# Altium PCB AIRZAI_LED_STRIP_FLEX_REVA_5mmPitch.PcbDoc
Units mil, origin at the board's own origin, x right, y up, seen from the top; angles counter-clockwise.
Board outline 6238.19 x 814.96 mil, 2 copper layers (Top Layer, Bottom Layer); 59 components, 60 nets, 298 pads, 62 vias.
Unrouted connection lines stored in the file: 83.
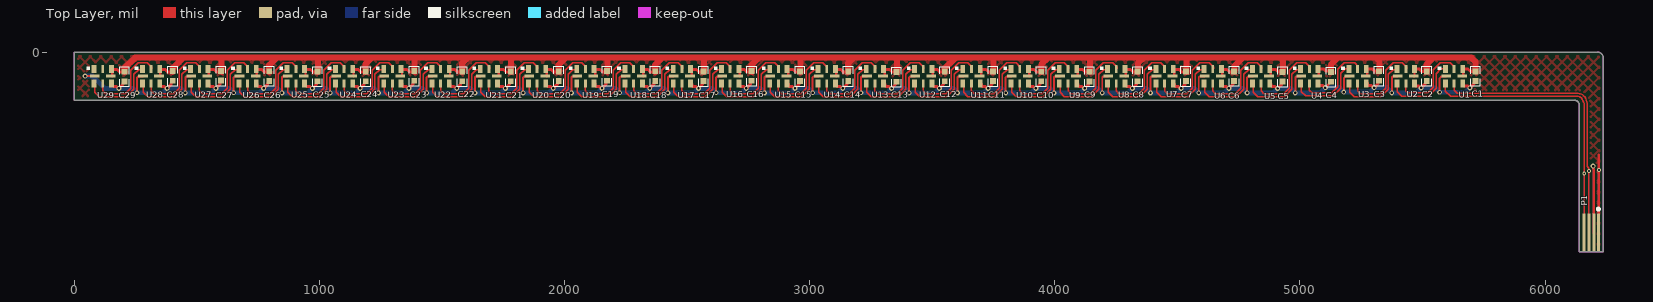
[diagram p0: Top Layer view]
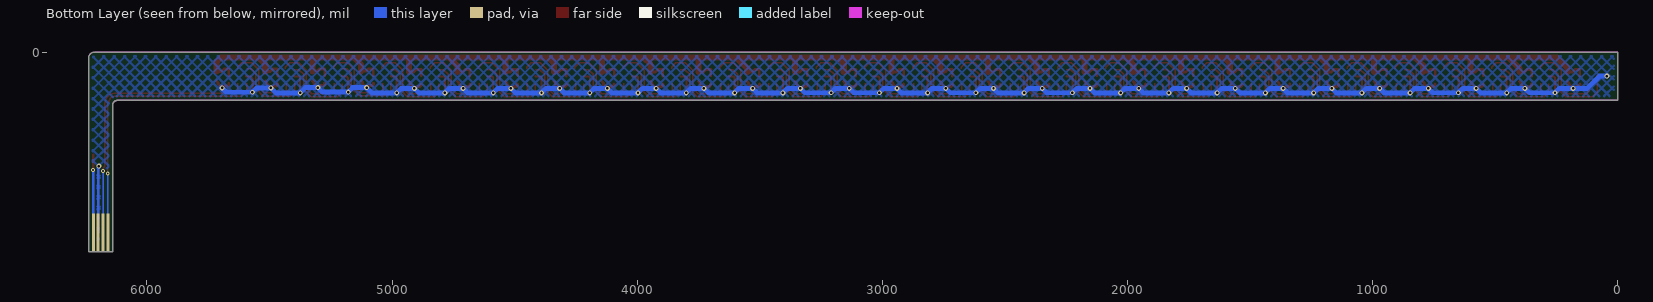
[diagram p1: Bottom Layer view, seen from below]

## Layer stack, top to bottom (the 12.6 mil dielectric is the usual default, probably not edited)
Top Solder: solder mask 0.4, Solder Resist, Dk 3.5
Top Layer: signal copper 1.4
Dielectric 1: dielectric 12.6, FR-4, Dk 4.8
Bottom Layer: signal copper 1.4
Bottom Solder: solder mask 0.4, Solder Resist, Dk 3.5

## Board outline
0,-196.85 0,0 6213.15,0 cw(c6213.15,-25.04) 6238.19,-25.04 6238.19,-814.96 6139.76,-814.96 6139.76,-216.54 ccw(c6120.08,-216.54) 6120.08,-196.85
board region "Layer Stack Region 1": 6238.19,-554.85 6238.19,-814.96 6139.76,-814.96 6139.76,-554.85
board region "Layer Stack Region 1": 6139.76,-522.85 6139.76,-216.54 6139.39,-212.7 6136.45,-205.6 6131.01,-200.17 6123.92,-197.23 6120.08,-196.85 0,-196.85 0,0 6213.15,0 6218.13,0 6227.33,-3.81 6234.38,-10.86 6238.19,-20.06 6238.19,-25.04 6238.19,-522.85
board region "Layer Stack Region 2": 6139.76,-554.85 6139.76,-522.85 6238.19,-522.85 6238.19,-554.85

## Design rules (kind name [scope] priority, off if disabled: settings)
Clearance Clearance_polygon_5V [OnLayer('Keep-Out Layer') vs (InNet('+5V') AND InPolygon)] p1: gap=10 ignorepadtopadclearanceinfootprint=FALSE
Clearance Clearance_POLYGON_KEEPOUT [(OnLayer('Keep-Out Layer')) vs (InNet('GND') AND InPolygon)] p2: gap=10 ignorepadtopadclearanceinfootprint=FALSE
Clearance [All] p3: gap=6 ignorepadtopadclearanceinfootprint=FALSE
MinimumSolderMaskSliver [All] p1: minsoldermaskwidth=1
PolygonConnect [All] p1: connectstyle=Direct reliefconductorwidth=10 reliefentries=4 polygonreliefangle="90 Angle" airgapwidth=10
RoomDefinition AIRZAI_LED_STRIP_FLEX_REVA_5mmPitch [InComponentClass('AIRZAI_LED_STRIP_FLEX_REVA_5mmPitch')] p1: confinementstyle=ConfineIn formatcopy=TRUE lockcomponents=FALSE outline -4184.14,-5323.29 10475.86,-5323.29 10475.86,4276.71 -4184.14,4276.71
RoutingVias [All] p1: holewidth=28 width=50 viastyle="Through Hole" minholewidth=8 minwidth=16 maxholewidth=28 maxwidth=50
SilkToSilkClearance [All] p1: silktosilkclearance=1
SilkToSolderMaskClearance [IsPad] p1: minsilkscreentomaskgap=2 clearancetoexposedcopper=TRUE
SolderMaskExpansion [All] p1: expansion=4
UnRoutedNet [All] p1: checkbadconnections=TRUE
Width [All] p1: maxlimit=100 minlimit=6 preferedwidth=10
26 further rules are at their usual default settings.

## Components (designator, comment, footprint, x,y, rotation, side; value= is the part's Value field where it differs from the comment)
C1 "0.1µF" 0402CAP 5716,-98.43 r270 top
C2 "0.1µF" 0402CAP 5517.17,-98.43 r270 top
C3 "0.1µF" 0402CAP 5322.3,-97.74 r270 top
C4 "0.1µF" 0402CAP 5126.94,-101.43 r270 top
C5 "0.1µF" 0402CAP 4929.6,-100.74 r270 top
C6 "0.1µF" 0402CAP 4731.75,-98.43 r270 top
C7 "0.1µF" 0402CAP 4534.9,-98.74 r270 top
C8 "0.1µF" 0402CAP 4338.05,-99.39 r270 top
C9 "0.1µF" 0402CAP 4142.2,-99.92 r270 top
C10 "0.1µF" 0402CAP 3945.35,-99.74 r270 top
C11 "0.1µF" 0402CAP 3748.17,-98.74 r270 top
C12 "0.1µF" 0402CAP 3551.65,-99.24 r270 top
C13 "0.1µF" 0402CAP 3354.8,-101.43 r270 top
C14 "0.1µF" 0402CAP 3157.43,-98.74 r270 top
C15 "0.1µF" 0402CAP 2961,-98.74 r270 top
C16 "0.1µF" 0402CAP 2763.62,-97.21 r270 top
C17 "0.1µF" 0402CAP 2567.39,-98.74 r270 top
C18 "0.1µF" 0402CAP 2370.54,-98.21 r270 top
C19 "0.1µF" 0402CAP 2174.13,-97.27 r270 top
C20 "0.1µF" 0402CAP 1976.84,-98.74 r270 top
C21 "0.1µF" 0402CAP 1780.99,-99.22 r270 top
C22 "0.1µF" 0402CAP 1583.39,-99.11 r270 top
C23 "0.1µF" 0402CAP 1387.29,-97.27 r270 top
C24 "0.1µF" 0402CAP 1189.44,-99.27 r270 top
C25 "0.1µF" 0402CAP 992.87,-98.95 r270 top
C26 "0.1µF" 0402CAP 796.06,-98.2 r270 top
C27 "0.1µF" 0402CAP 599.32,-96.9 r270 top
C28 "0.1µF" 0402CAP 402.72,-97.42 r270 top
C29 "0.1µF" 0402CAP 205.62,-100.39 r270 top
P1 "Header 4" FFC_4PADS 6188.98,-736.24 r0 top
U1 "APA102-2020-256-8" APA102–2020 5629,-98.43 r270 top
U2 "APA102-2020-256-8" APA102–2020 5432,-98.43 r270 top
U3 "APA102-2020-256-8" APA102–2020 5235.3,-98.43 r270 top
U4 "APA102-2020-256-8" APA102–2020 5038.45,-98.43 r270 top
U5 "APA102-2020-256-8" APA102–2020 4841.6,-98.43 r270 top
U6 "APA102-2020-256-8" APA102–2020 4644.75,-98.43 r270 top
U7 "APA102-2020-256-8" APA102–2020 4447.9,-98.43 r270 top
U8 "APA102-2020-256-8" APA102–2020 4251.05,-98.43 r270 top
U9 "APA102-2020-256-8" APA102–2020 4054.2,-98.42 r270 top
U10 "APA102-2020-256-8" APA102–2020 3857.35,-98.43 r270 top
U11 "APA102-2020-256-8" APA102–2020 3660.5,-98.42 r270 top
U12 "APA102-2020-256-8" APA102–2020 3463.65,-98.43 r270 top
U13 "APA102-2020-256-8" APA102–2020 3266.8,-98.42 r270 top
U14 "APA102-2020-256-8" APA102–2020 3070,-98.42 r270 top
U15 "APA102-2020-256-8" APA102–2020 2873,-98.43 r270 top
U16 "APA102-2020-256-8" APA102–2020 2676.24,-98.42 r270 top
U17 "APA102-2020-256-8" APA102–2020 2479.39,-98.43 r270 top
U18 "APA102-2020-256-8" APA102–2020 2282.54,-98.42 r270 top
U19 "APA102-2020-256-8" APA102–2020 2085.69,-98.43 r270 top
U20 "APA102-2020-256-8" APA102–2020 1888.84,-98.43 r270 top
U21 "APA102-2020-256-8" APA102–2020 1691.99,-98.43 r270 top
U22 "APA102-2020-256-8" APA102–2020 1495.14,-98.43 r270 top
U23 "APA102-2020-256-8" APA102–2020 1298.29,-98.43 r270 top
U24 "APA102-2020-256-8" APA102–2020 1101.44,-98.43 r270 top
U25 "APA102-2020-256-8" APA102–2020 904.59,-98.43 r270 top
U26 "APA102-2020-256-8" APA102–2020 707.74,-98.42 r270 top
U27 "APA102-2020-256-8" APA102–2020 510.89,-98.43 r270 top
U28 "APA102-2020-256-8" APA102–2020 314.04,-98.42 r270 top
U29 "APA102-2020-256-8" APA102–2020 117.19,-98.42 r270 top

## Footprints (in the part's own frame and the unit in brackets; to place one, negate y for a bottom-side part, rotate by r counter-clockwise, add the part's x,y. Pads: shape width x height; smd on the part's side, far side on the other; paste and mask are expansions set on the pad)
0402CAP [mm] "Chip Capacitor, Body 1.1x0.5mm, IPC High Density"
  rect 0.6x0.6 smd: 1(-0.5,0) 2(0.5,0)
  silkscreen extent -1.02,-0.51 1.02,0.51, body extent -0.5,-0.3 0.5,0.3, height 0.19
APA102–2020 [mm]
  rect 0.8x0.5 smd: 1(-0.75,0.9) 3(-0.75,-0.9) 4(0.75,-0.9) 6(0.75,0.9)
  rect 0.8x0.3 smd: 2(-0.75,0) 5(0.75,0)
  rect 0.3x1 smd: 7(0,-0.83) 8(0,0.83)
  silkscreen extent -1.02,-1.7 -0.63,-1.32, body extent -1,-1 1,1, height 0.94
FFC_4PADS [mm] "(0.50mm"
  rect 0.3x4 smd: 1(0.75,0) 2(0.25,0) 3(-0.25,0) 4(-0.75,0)
  rect 0.3x4 smd far side: 1(0.75,0) 2(0.25,0) 3(-0.25,0) 4(-0.75,0)
  silkscreen extent 0.61,2.31 0.86,2.56

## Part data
C1 C2 C3 C4 C5 C6 C7 C8 C9 C10 C11 C12 C13 C14 C15 C16 C17 C18 C19 C20 C21 C22 C23 C24 C25 C26 C27 C28 C29: library part C0402-100n, "Capacitor, X7R, ±10%", Case-EIA=0402, Case-Metric=1005, Manufacturer=TDK, Manufacturer Part Number=C1005X7R1C104K, Rated Voltage="16 V", Supplier Part Number 1=445-4952-2-ND, Tolerance=±20%
P1: "Header, 4-Pin"
U1 U2 U3 U4 U5 U6 U7 U8 U9 U10 U11 U12 U13 U14 U15 U16 U17 U18 U19 U20 U21 U22 U23 U24 U25 U26 U27 U28 U29: "DotStar Micro LEDs", Package="SOIC-20 Adafruit Industries"

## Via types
v1: diameter 20, hole 10, Top Layer to Bottom Layer, tented both sides, 59 vias
v2: diameter 16, hole 8, Top Layer to Bottom Layer, tented both sides, 3 vias

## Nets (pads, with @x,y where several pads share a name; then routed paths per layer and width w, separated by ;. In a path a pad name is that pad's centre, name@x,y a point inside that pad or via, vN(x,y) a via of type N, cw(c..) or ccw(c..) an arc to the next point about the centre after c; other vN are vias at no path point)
+5V: C1.1 C2.1 C3.1 C4.1 C5.1 C6.1 C7.1 C8.1 C9.1 C10.1 C11.1 C12.1 C13.1 C14.1 C15.1 C16.1 C17.1 C18.1 C19.1 C20.1 C21.1 C22.1 C23.1 C24.1 C25.1 C26.1 C27.1 C28.1 C29.1 P1.1 U1.1 U1.8 U2.1 U2.8 U3.1 U3.8 U4.1 U4.8 U5.1 U5.8 U6.1 U6.8 U7.1 U7.8 U8.1 U8.8 U9.1 U9.8 U10.1 U10.8 U11.1 U11.8 U12.1 U12.8 U13.1 U13.8 U14.1 U14.8 U15.1 U15.8 U16.1 U16.8 U17.1 U17.8 U18.1 U18.8 U19.1 U19.8 U20.1 U20.8 U21.1 U21.8 U22.1 U22.8 U23.1 U23.8 U24.1 U24.8 U25.1 U25.8 U26.1 U26.8 U27.1 U27.8 U28.1 U28.8 U29.1 U29.8 | length 10646.1
  Top Layer w10: U29.8@155.47,-98.42 U29.1@155.47,-71.21 ; U28.8@352.32,-98.43 U28.1@352.32,-71.21 ; U27.8@550.25,-96.85 U27.1@550.25,-71.21 ; U26.8@746.02,-98.43 U26.1@746.02,-71.21 ; U25.8@943.95,-96.85 U25.1@943.95,-71.21 ; U24.8@1139.72,-98.43 U24.1@1139.72,-71.21 ; U23.8@1337.65,-96.85 U23.1@1337.65,-71.21 ; U22.8@1533.42,-98.43 U22.1@1533.42,-71.21 ; U21.8@1731.35,-96.85 U21.1@1731.35,-71.21 ; U20.8@1927.12,-98.43 U20.1@1927.12,-71.21 ; U19.8@2125.05,-96.85 U19.1@2125.05,-71.21 ; U18.8@2320.82,-98.43 U18.1@2320.82,-71.21 ; U17.8@2518.75,-96.85 U17.1@2518.75,-71.21 ; U16.8@2714.43,-98.43 U16.1@2714.43,-71.21 ; U15.8@2912.36,-96.85 U15.1@2912.36,-71.21 ; U14.8@3108.22,-98.42 U14.1@3108.22,-71.21 ; U13.8@3306.15,-96.85 U13.1@3306.15,-71.21 ; U12.8@3501.92,-98.42 U12.1@3501.92,-71.21 ; U11.8@3699.85,-96.85 U11.1@3699.85,-71.21 ; U10.8@3895.62,-98.42 U10.1@3895.62,-71.21 ; U9.8@4093.55,-96.85 U9.1@4093.55,-71.21 ; U8.8@4289.32,-98.43 U8.1@4289.32,-71.21 ; U7.8@4487.25,-96.85 U7.1@4487.25,-71.21 ; U6.8@4683.03,-98.43 U6.1@4683.03,-71.21 ; U5.8@4880.95,-96.85 U5.1@4880.95,-71.21 ; U4.8@5073.97,-97.74 5075.82,-97.74 5076.73,-96.83 U4.1@5076.73,-68.21 ; U3.8@5274.66,-97.74 5275.56,-96.83 U3.1@5275.56,-68.21 ; U2.8 5466.53,-98.43 5467.43,-97.52 U2.1 ; U1.8@5665.36,-98.43 5666.27,-97.52 U1.1@5666.27,-68.9 ; P1.1@6218.5,-736.24 6218.5,-486.35 6218.62,-486.24 6218.62,-482 v2(6219.76,-480.85) 6219.76,-417.85
  Top Layer w12: U29.1@155.47,-71.21 175.11,-71.21 184.95,-81.05 C29.1@205.2,-81.05 ; U28.1@352.32,-71.21 371.96,-71.21 381.8,-81.05 C28.1@402.05,-81.05 ; U27.1@550.25,-71.21 570.8,-71.21 580.64,-81.05 C27.1@600.88,-81.05 ; U26.1@746.02,-71.21 765.66,-71.21 775.51,-81.05 C26.1@795.75,-81.05 ; U25.1@943.95,-71.21 964.5,-71.21 974.34,-81.05 C25.1@994.58,-81.05 ; U24.1@1139.72,-71.21 1159.36,-71.21 1169.21,-81.05 C24.1@1189.45,-81.05 ; U23.1@1337.65,-71.21 1358.2,-71.21 1368.04,-81.05 C23.1@1388.28,-81.05 ; U22.1@1533.42,-71.21 1553.06,-71.21 1562.91,-81.05 C22.1@1583.15,-81.05 ; U21.1@1731.35,-71.21 1751.9,-71.21 1761.74,-81.05 C21.1@1781.99,-81.05 ; U20.1@1927.12,-71.21 1946.77,-71.21 1956.61,-81.05 C20.1@1976.85,-81.05 ; U19.1@2125.05,-71.21 2145.6,-71.21 2155.44,-81.05 C19.1@2175.69,-81.05 ; U18.1@2320.82,-71.21 2340.47,-71.21 2350.31,-81.05 C18.1@2370.55,-81.05 ; U17.1@2518.75,-71.21 2539.3,-71.21 2549.14,-81.05 C17.1@2569.39,-81.05 ; U16.1@2714.43,-71.21 2734.07,-71.21 2743.91,-81.05 C16.1@2764.16,-81.05 ; U15.1@2912.36,-71.21 2932.91,-71.21 2942.75,-81.05 C15.1@2962.99,-81.05 ; U14.1@3108.22,-71.21 3127.87,-71.21 3137.71,-81.05 C14.1@3157.96,-81.05 ; U13.1@3306.15,-71.21 3326.7,-71.21 3336.55,-81.05 C13.1@3356.79,-81.05 ; U12.1@3501.92,-71.21 3521.57,-71.21 3531.41,-81.05 C12.1@3551.66,-81.05 ; U11.1@3699.85,-71.21 3720.4,-71.21 3730.25,-81.05 C11.1@3750.49,-81.05 ; U10.1@3895.62,-71.21 3915.27,-71.21 3925.11,-81.05 C10.1@3945.36,-81.05 ; U9.1@4093.55,-71.21 4114.1,-71.21 4123.95,-81.05 C9.1@4144.19,-81.05 ; U8.1@4289.32,-71.21 4308.97,-71.21 4318.81,-81.05 C8.1@4339.06,-81.05 ; U7.1@4487.25,-71.21 4507.8,-71.21 4517.65,-81.05 C7.1@4537.89,-81.05 ; U6.1@4683.03,-71.21 4702.67,-71.21 4712.51,-81.05 C6.1@4732.76,-81.05 ; U5.1@4880.95,-71.21 4901.51,-71.21 4911.35,-81.05 C5.1@4931.59,-81.05 ; U4.1@5076.73,-68.21 5096.37,-68.21 5106.21,-78.05 C4.1@5126.46,-78.05 ; U3.1@5275.56,-68.21 5295.21,-68.21 5305.05,-78.05 C3.1@5325.29,-78.05 ; U2.1 5487.08,-68.9 5496.92,-78.74 C2.1 ; U1.1@5666.27,-68.9 5685.91,-68.9 5695.76,-78.74 C1.1
  Top Layer w25: C29.1@205.2,-81.05 205.2,-66.86 249.41,-22.65 472.76,-22.65 ; C28.1@402.05,-81.05 402.05,-66.86 446.26,-22.65 472.76,-22.65 ; C27.1@600.88,-81.05 600.88,-28.97 594.56,-22.65 ; C26.1@795.75,-81.05 795.75,-53.01 826.11,-22.65 ; C25.1@994.58,-81.05 994.58,-24.67 992.56,-22.65 ; C24.1@1189.45,-81.05 1189.45,-48.46 1215.26,-22.65 ; 1381.34,-22.65 1388.28,-29.59 C23.1@1388.28,-81.05 ; C22.1@1583.15,-81.05 1583.15,-45.76 1606.26,-22.65 1608.96,-22.65 ; C21.1@1781.99,-81.05 1781.99,-25.29 1779.34,-22.65 ; C20.1@1976.85,-81.05 1976.85,-52.16 2006.37,-22.65 ; C19.1@2175.69,-81.05 2175.69,-26.37 2171.96,-22.65 ; C18.1@2370.55,-81.05 2370.55,-52.06 2399.96,-22.65 ; C17.1@2569.39,-81.05 2569.39,-28.47 2563.56,-22.65 ; C16.1@2764.16,-81.05 2764.16,-51.75 2793.26,-22.65 ; C15.1@2962.99,-81.05 2962.99,-28.08 2957.56,-22.65 ; C14.1@3157.96,-81.05 3157.96,-44.66 3179.96,-22.65 ; C13.1@3356.79,-81.05 3356.79,-24.88 3354.56,-22.65 ; C12.1@3551.66,-81.05 3551.66,-66.86 3595.86,-22.65 ; 3743.29,-22.65 3750.49,-29.85 C11.1@3750.49,-81.05 ; C10.1@3945.36,-81.05 3945.36,-50.68 3973.39,-22.65 ; C9.1@4144.19,-81.05 4144.19,-22.65 ; C8.1@4339.06,-81.05 4339.06,-46.56 4362.96,-22.65 4450.89,-22.65 ; C7.1@4537.89,-81.05 4537.89,-27.98 4532.56,-22.65 4450.89,-22.65 ; C6.1@4732.76,-81.05 4732.76,-57.86 4767.96,-22.65 4894.76,-22.65 ; C5.1@4931.59,-81.05 4931.59,-22.65 4894.76,-22.65 ; C4.1@5126.46,-78.05 5126.46,-51.08 5150.33,-27.21 ; C3.1@5325.29,-78.05 5325.29,-38.4 5309.55,-22.65 ; C2.1 5517.17,-50.63 5544.35,-23.44 5543.56,-22.65 ; C1.1 5716,-39.09 5699.56,-22.65 5543.56,-22.65 ; 472.76,-22.65 594.56,-22.65 ; 594.56,-22.65 826.11,-22.65 ; 826.11,-22.65 992.56,-22.65 ; 992.56,-22.65 1608.96,-22.65 ; 1608.96,-22.65 1779.34,-22.65 ; 1779.34,-22.65 2006.37,-22.65 ; 2006.37,-22.65 2171.96,-22.65 ; 2171.96,-22.65 2399.96,-22.65 ; 2399.96,-22.65 2563.56,-22.65 ; 2563.56,-22.65 2793.26,-22.65 ; 2793.26,-22.65 2957.56,-22.65 ; 2957.56,-22.65 3179.96,-22.65 ; 3179.96,-22.65 3232.76,-22.65 3354.56,-22.65 ; 3354.56,-22.65 3595.86,-22.65 ; 3595.86,-22.65 3973.39,-22.65 ; 3973.39,-22.65 4144.19,-22.65 ; 4144.19,-22.65 4450.89,-22.65 ; 4450.89,-22.65 4894.76,-22.65 ; 4894.76,-22.65 5309.55,-22.65 ; 5309.55,-22.65 5543.56,-22.65
  Bottom Layer w10: P1.1@6218.5,-736.24 6218.5,-486.35 6218.62,-486.24 6218.62,-482.22 6218.5,-482.11 v2(6219.76,-480.85)
GND: C1.2 C2.2 C3.2 C4.2 C5.2 C6.2 C7.2 C8.2 C9.2 C10.2 C11.2 C12.2 C13.2 C14.2 C15.2 C16.2 C17.2 C18.2 C19.2 C20.2 C21.2 C22.2 C23.2 C24.2 C25.2 C26.2 C27.2 C28.2 C29.2 P1.2 U1.6 U1.7 U2.6 U2.7 U3.6 U3.7 U4.6 U4.7 U5.6 U5.7 U6.6 U6.7 U7.6 U7.7 U8.6 U8.7 U9.6 U9.7 U10.6 U10.7 U11.6 U11.7 U12.6 U12.7 U13.6 U13.7 U14.6 U14.7 U15.6 U15.7 U16.6 U16.7 U17.6 U17.7 U18.6 U18.7 U19.6 U19.7 U20.6 U20.7 U21.6 U21.7 U22.6 U22.7 U23.6 U23.7 U24.6 U24.7 U25.6 U25.7 U26.6 U26.7 U27.6 U27.7 U28.6 U28.7 U29.6 U29.7 | length 11347.9
  Top Layer w8: v1(44.76,-98.43) U29.7 ; v1(256.8,-166.16) 256.8,-103.26 259.72,-100.33 279.46,-100.33 U28.7 ; v1(453.65,-166.16) 453.65,-103.26 456.57,-100.33 476.31,-100.33 U27.7 ; v1(650.5,-166.16) 650.5,-103.26 653.43,-100.33 673.16,-100.33 U26.7 ; v1(847.35,-166.16) 847.35,-103.26 850.28,-100.33 870.01,-100.33 U25.7 ; v1(1044.2,-166.16) 1044.2,-103.26 1047.13,-100.33 1066.86,-100.33 U24.7 ; v1(1241.05,-166.16) 1241.05,-103.26 1243.98,-100.33 1263.71,-100.33 U23.7 ; v1(1437.9,-166.16) 1437.9,-103.26 1440.83,-100.33 1460.56,-100.33 U22.7 ; v1(1634.75,-166.16) 1634.75,-103.26 1637.68,-100.33 1657.41,-100.33 U21.7 ; v1(1831.6,-166.16) 1831.6,-103.26 1834.53,-100.33 1854.26,-100.33 U20.7 ; v1(2028.45,-166.16) 2028.45,-103.26 2031.38,-100.33 2051.11,-100.33 U19.7 ; v1(2225.3,-166.16) 2225.3,-103.26 2228.23,-100.33 2247.96,-100.33 U18.7 ; v1(2422.15,-166.16) 2422.15,-103.26 2425.08,-100.33 2444.81,-100.33 U17.7 ; v1(2619,-166.16) 2619,-103.26 2621.93,-100.33 2641.66,-100.33 U16.7 ; v1(2815.76,-166.16) 2815.76,-103.26 2818.69,-100.33 2838.42,-100.33 U15.7 ; v1(3012.76,-166.16) 3012.76,-103.26 3015.69,-100.33 3035.42,-100.33 U14.7 ; v1(3209.55,-166.16) 3209.55,-103.26 3212.48,-100.33 3232.21,-100.33 U13.7 ; v1(3406.4,-166.16) 3406.4,-103.26 3409.33,-100.33 3429.06,-100.33 U12.7 ; v1(3603.25,-166.16) 3603.25,-103.26 3606.18,-100.33 3625.91,-100.33 U11.7 ; v1(3800.1,-166.16) 3800.1,-103.26 3803.03,-100.33 3822.76,-100.33 U10.7 ; v1(3996.96,-166.16) 3996.96,-103.26 3999.88,-100.33 4019.62,-100.33 U9.7 ; v1(4193.8,-166.16) 4193.8,-103.26 4196.73,-100.33 4216.46,-100.33 U8.7 ; v1(4390.66,-166.16) 4390.66,-103.26 4393.58,-100.33 4413.31,-100.33 U7.7 ; v1(4587.51,-166.16) 4587.51,-103.26 4590.43,-100.33 4610.17,-100.33 U6.7 ; v1(4784.36,-166.16) 4784.36,-103.26 4787.28,-100.33 4807.02,-100.33 U5.7 ; v1(4981.21,-166.16) 4981.21,-103.26 4984.13,-100.33 5003.87,-100.33 U4.7 ; v1(5179.06,-163.16) 5179.06,-106.16 5184.89,-100.33 5200.72,-100.33 U3.7 ; U3.7@5203.71,-99.64 U3.7@5205.62,-97.74 ; v1(5374.76,-166.16) 5374.76,-103.26 5377.69,-100.33 5397.42,-100.33 U2.7 ; v1(5569.76,-163.85) 5569.76,-106.85 5576.28,-100.33 5594.42,-100.33 U1.7
  Top Layer w10: v1@6197.68,-466.76 v1(6195.76,-464.85) 6195.76,-474.85 6198.82,-477.91 P1.2@6198.82,-736.24
  Top Layer w12: U29.6@155.47,-130.26 155.47,-136.17 159.31,-140.01 172.48,-140.01 180.63,-148.16 v1(182.8,-148.16) 199.39,-131.57 199.39,-126.23 C29.2@205.2,-120.42 ; U28.6@352.32,-130.26 352.32,-136.17 356.16,-140.01 369.33,-140.01 377.48,-148.16 v1(379.65,-148.16) 396.24,-131.57 396.24,-126.23 C28.2@402.05,-120.42 ; U27.6@551.15,-130.26 551.15,-136.17 554.99,-140.01 568.17,-140.01 576.32,-148.16 v1(578.48,-148.16) 595.07,-131.57 595.07,-126.23 C27.2@600.88,-120.42 ; U26.6@746.02,-130.26 746.02,-136.17 749.86,-140.01 763.03,-140.01 771.18,-148.16 v1(773.35,-148.16) 789.94,-131.57 789.94,-126.23 C26.2@795.75,-120.42 ; U25.6@944.85,-130.26 944.85,-136.17 948.69,-140.01 961.87,-140.01 970.02,-148.16 v1(972.18,-148.16) 988.77,-131.57 988.77,-126.23 C25.2@994.58,-120.42 ; U24.6@1139.72,-130.26 1139.72,-136.17 1143.56,-140.01 1156.73,-140.01 1164.88,-148.16 v1(1167.05,-148.16) 1183.64,-131.57 1183.64,-126.23 C24.2@1189.45,-120.42 ; U23.6@1338.55,-130.26 1338.55,-136.17 1342.4,-140.01 1355.57,-140.01 1363.72,-148.16 v1(1365.88,-148.16) 1382.47,-131.57 1382.47,-126.23 C23.2@1388.28,-120.42 ; U22.6@1533.42,-130.26 1533.42,-136.17 1537.26,-140.01 1550.44,-140.01 1558.58,-148.16 v1(1560.75,-148.16) 1577.34,-131.57 1577.34,-126.23 C22.2@1583.15,-120.42 ; U21.6@1732.25,-130.26 1732.25,-136.17 1736.1,-140.01 1749.27,-140.01 1757.42,-148.16 v1(1759.58,-148.16) 1776.17,-131.57 1776.17,-126.23 C21.2@1781.99,-120.42 ; U20.6@1927.12,-130.26 1927.12,-136.17 1930.96,-140.01 1944.14,-140.01 1952.29,-148.16 v1(1954.45,-148.16) 1971.04,-131.57 1971.04,-126.23 C20.2@1976.85,-120.42 ; U19.6@2125.95,-130.26 2125.95,-136.17 2129.8,-140.01 2142.97,-140.01 2151.12,-148.16 v1(2153.28,-148.16) 2169.88,-131.57 2169.88,-126.23 C19.2@2175.69,-120.42 ; U18.6@2320.82,-130.26 2320.82,-136.17 2324.66,-140.01 2337.84,-140.01 2345.99,-148.16 v1(2348.15,-148.16) 2364.74,-131.57 2364.74,-126.23 C18.2@2370.55,-120.42 ; U17.6@2519.66,-130.26 2519.66,-136.17 2523.5,-140.01 2536.67,-140.01 2544.82,-148.16 v1(2546.99,-148.16) 2563.58,-131.57 2563.58,-126.23 C17.2@2569.39,-120.42 ; U16.6@2714.43,-130.26 2714.43,-136.17 2718.27,-140.01 2731.44,-140.01 2739.59,-148.16 v1(2741.76,-148.16) 2758.35,-131.57 2758.35,-126.23 C16.2@2764.16,-120.42 ; U15.6@2913.26,-130.26 2913.26,-136.17 2917.1,-140.01 2930.28,-140.01 2938.43,-148.16 v1(2940.59,-148.16) 2957.18,-131.57 2957.18,-126.23 C15.2@2962.99,-120.42 ; U14.6@3108.22,-130.26 3108.22,-136.17 3112.07,-140.01 3125.24,-140.01 3133.39,-148.16 v1(3135.55,-148.16) 3152.14,-131.57 3152.14,-126.23 C14.2@3157.96,-120.42 ; U13.6@3307.06,-130.26 3307.06,-136.17 3310.9,-140.01 3324.07,-140.01 3332.22,-148.16 v1(3334.39,-148.16) 3350.98,-131.57 3350.98,-126.23 C13.2@3356.79,-120.42 ; U12.6@3501.92,-130.26 3501.92,-136.17 3505.77,-140.01 3518.94,-140.01 3527.09,-148.16 v1(3529.25,-148.16) 3545.84,-131.57 3545.84,-126.23 C12.2@3551.66,-120.42 ; U11.6@3700.76,-130.26 3700.76,-136.17 3704.6,-140.01 3717.77,-140.01 3725.92,-148.16 v1(3728.09,-148.16) 3744.68,-131.57 3744.68,-126.23 C11.2@3750.49,-120.42 ; U10.6@3895.62,-130.26 3895.62,-136.17 3899.47,-140.01 3912.64,-140.01 3920.79,-148.16 v1(3922.96,-148.16) 3939.55,-131.57 3939.55,-126.23 C10.2@3945.36,-120.42 ; U9.6@4094.46,-130.26 4094.46,-136.17 4098.3,-140.01 4111.48,-140.01 4119.63,-148.16 v1(4121.79,-148.16) 4138.38,-131.57 4138.38,-126.23 C9.2@4144.19,-120.42 ; U8.6@4289.32,-130.26 4289.32,-136.17 4293.17,-140.01 4306.34,-140.01 4314.49,-148.16 v1(4316.66,-148.16) 4333.25,-131.57 4333.25,-126.23 C8.2@4339.06,-120.42 ; U7.6@4488.16,-130.26 4488.16,-136.17 4492,-140.01 4505.18,-140.01 4513.32,-148.16 v1(4515.49,-148.16) 4532.08,-131.57 4532.08,-126.23 C7.2@4537.89,-120.42 ; U6.6@4683.03,-130.26 4683.03,-136.17 4686.87,-140.01 4700.04,-140.01 4708.19,-148.16 v1(4710.36,-148.16) 4726.95,-131.57 4726.95,-126.23 C6.2@4732.76,-120.42 ; U5.6@4881.86,-130.26 4881.86,-136.17 4885.7,-140.01 4898.88,-140.01 4907.03,-148.16 v1(4909.19,-148.16) 4925.78,-131.57 4925.78,-126.23 C5.2@4931.59,-120.42 ; U4.6@5076.73,-127.26 5076.73,-133.17 5080.57,-137.01 5093.74,-137.01 5101.89,-145.16 v1(5104.06,-145.16) 5120.65,-128.57 5120.65,-123.23 C4.2@5126.46,-117.42 ; U3.6@5275.56,-127.26 5275.56,-133.17 5279.4,-137.01 5292.58,-137.01 5300.73,-145.16 v1(5302.89,-145.16) 5319.48,-128.57 5319.48,-123.23 C3.2@5325.29,-117.42 ; U2.6 5467.43,-133.86 5471.28,-137.7 5484.45,-137.7 5492.6,-145.85 v1(5494.76,-145.85) 5511.35,-129.26 5511.35,-123.92 C2.2 ; U1.6@5666.27,-127.95 5666.27,-133.86 5670.11,-137.7 5683.28,-137.7 5691.43,-145.85 v1(5693.6,-145.85) 5710.19,-129.26 5710.19,-123.92 C1.2
  Bottom Layer w10: P1.2@6198.82,-736.24 6198.82,-474.98
  Bottom Layer w20: v1(44.76,-98.43) 75.34,-98.43 125.07,-148.16 v1(182.8,-148.16) 238.8,-148.16 v1(256.8,-166.16) 361.65,-166.16 v1(379.65,-148.16) 435.65,-148.16 v1(453.65,-166.16) 560.48,-166.16 v1(578.48,-148.16) 632.5,-148.16 v1(650.5,-166.16) 755.35,-166.16 v1(773.35,-148.16) 829.35,-148.16 v1(847.35,-166.16) 954.18,-166.16 v1(972.18,-148.16) 1026.2,-148.16 v1(1044.2,-166.16) 1149.05,-166.16 v1(1167.05,-148.16) 1223.05,-148.16 v1(1241.05,-166.16) 1347.88,-166.16 v1(1365.88,-148.16) 1419.9,-148.16 v1(1437.9,-166.16) 1542.75,-166.16 v1(1560.75,-148.16) 1616.75,-148.16 v1(1634.75,-166.16) 1741.58,-166.16 v1(1759.58,-148.16) 1813.6,-148.16 v1(1831.6,-166.16) 1936.45,-166.16 v1(1954.45,-148.16) 2010.45,-148.16 v1(2028.45,-166.16) 2135.28,-166.16 v1(2153.28,-148.16) 2207.3,-148.16 v1(2225.3,-166.16) 2330.15,-166.16 v1(2348.15,-148.16) 2404.15,-148.16 v1(2422.15,-166.16) 2528.99,-166.16 v1(2546.99,-148.16) 2601,-148.16 v1(2619,-166.16) 2723.76,-166.16 v1(2741.76,-148.16) 2797.76,-148.16 v1(2815.76,-166.16) 2922.59,-166.16 v1(2940.59,-148.16) 2994.76,-148.16 v1(3012.76,-166.16) 3117.55,-166.16 v1(3135.55,-148.16) 3191.55,-148.16 v1(3209.55,-166.16) 3316.39,-166.16 v1(3334.39,-148.16) 3388.4,-148.16 v1(3406.4,-166.16) 3511.25,-166.16 v1(3529.25,-148.16) 3585.25,-148.16 v1(3603.25,-166.16) 3710.09,-166.16 v1(3728.09,-148.16) 3782.1,-148.16 v1(3800.1,-166.16) 3904.96,-166.16 v1(3922.96,-148.16) 3978.96,-148.16 v1(3996.96,-166.16) 4103.79,-166.16 v1(4121.79,-148.16) 4175.8,-148.16 v1(4193.8,-166.16) 4298.66,-166.16 v1(4316.66,-148.16) 4372.66,-148.16 v1(4390.66,-166.16) 4497.49,-166.16 v1(4515.49,-148.16) 4569.51,-148.16 v1(4587.51,-166.16) 4692.36,-166.16 v1(4710.36,-148.16) 4766.36,-148.16 v1(4784.36,-166.16) 4891.19,-166.16 v1(4909.19,-148.16) 4963.21,-148.16 v1(4981.21,-166.16) 5083.06,-166.16 v1(5104.06,-145.16) 5161.06,-145.16 v1(5179.06,-163.16) 5284.89,-163.16 v1(5302.89,-145.16) 5353.76,-145.16 v1(5374.76,-166.16) 5474.45,-166.16 v1(5494.76,-145.85) 5551.76,-145.85 v1(5569.76,-163.85) 5675.6,-163.85 v1(5693.6,-145.85)
LED_CLK_IN: P1.3 U1.5 | length 1379.3
  Top Layer w6: U1.5 5629,-156.09 5641.76,-168.85 6135.04,-168.85 cw(c6135.04,-199.58) 6156.76,-177.85 cw(c6118.14,-216.48) 6172.76,-216.48 6172.76,-463.19 ccw(c6186.42,-463.19) 6176.76,-472.85 cw(c6171.04,-478.57) 6179.13,-478.57 v2(6179.13,-484.85) P1.3@6179.13,-736.24
  Bottom Layer w6: P1.3@6179.13,-736.24 v2(6179.13,-484.85)
LED_CLK_OUT1: U1.2 U2.5 | length 339.5
  Top Layer w6: U2.5 5432,-158.7 5440.15,-166.85 5520.76,-166.85 5544.26,-143.35 5544.26,-71.35 5571.46,-44.15 5613.06,-44.15 5629,-60.09 U1.2
LED_CLK_OUT2: U2.2 U3.5 | length 342.6
  Top Layer w6: U3.5@5235.15,-127.95 5235.15,-158.17 5246.14,-169.16 5326.76,-169.16 5349.17,-146.75 5349.17,-74.75 5379.77,-44.15 5416.75,-44.15 5434.99,-62.4 U2.2@5434.99,-68.9
LED_CLK_OUT3: U3.2 U4.5 | length 339.5
  Top Layer w6: U4.5 5038.45,-155.17 5049.44,-166.16 5130.06,-166.16 5154.06,-142.16 5154.06,-70.16 5180.07,-44.15 5223.05,-44.15 5238.29,-59.4 U3.2@5238.29,-68.21
LED_CLK_OUT4: U4.2 U5.5 | length 342.6
  Top Layer w6: U5.5 4841.6,-158.17 4852.59,-169.16 4933.21,-169.16 4955.61,-146.75 4955.61,-74.75 4986.22,-44.15 5023.2,-44.15 5041.44,-62.4 U4.2@5041.44,-68.9
LED_CLK_OUT5: U5.2 U6.5 | length 342.6
  Top Layer w6: U6.5 4644.75,-158.17 4655.74,-169.16 4736.36,-169.16 4758.76,-146.75 4758.76,-74.75 4789.37,-44.15 4826.34,-44.15 4844.59,-62.4 U5.2@4844.59,-68.9
LED_CLK_OUT6: U6.2 U7.5 | length 342.6
  Top Layer w6: U7.5 4447.9,-158.17 4458.89,-169.16 4539.51,-169.16 4561.91,-146.75 4561.91,-74.75 4592.52,-44.15 4629.49,-44.15 4647.74,-62.4 U6.2@4647.74,-68.9
LED_CLK_OUT7: U7.2 U8.5 | length 342.6
  Top Layer w6: U8.5 4251.05,-158.17 4262.04,-169.16 4342.66,-169.16 4365.06,-146.75 4365.06,-74.75 4395.67,-44.15 4432.64,-44.15 4450.89,-62.4 U7.2@4450.89,-68.9
LED_CLK_OUT8: U8.2 U9.5 | length 342.6
  Top Layer w6: U9.5 4054.2,-158.17 4065.19,-169.16 4145.8,-169.16 4168.21,-146.75 4168.21,-74.75 4198.82,-44.15 4235.79,-44.15 4254.04,-62.4 U8.2@4254.04,-68.9
LED_CLK_OUT9: U9.2 U10.5 | length 342.6
  Top Layer w6: U10.5 3857.35,-158.17 3868.34,-169.16 3948.96,-169.16 3971.36,-146.75 3971.36,-74.75 4001.97,-44.15 4038.94,-44.15 4057.19,-62.4 U9.2@4057.19,-68.9
LED_CLK_OUT10: U10.2 U11.5 | length 342.6
  Top Layer w6: U11.5 3660.5,-158.17 3671.49,-169.16 3752.1,-169.16 3774.51,-146.75 3774.51,-74.75 3805.12,-44.15 3842.09,-44.15 3860.34,-62.4 U10.2@3860.34,-68.9
LED_CLK_OUT11: U11.2 U12.5 | length 342.6
  Top Layer w6: U12.5 3463.65,-158.17 3474.64,-169.16 3555.25,-169.16 3577.66,-146.75 3577.66,-74.75 3608.26,-44.15 3645.24,-44.15 3663.49,-62.4 U11.2@3663.49,-68.9
LED_CLK_OUT12: U12.2 U13.5 | length 342.6
  Top Layer w6: U13.5 3266.8,-158.17 3277.79,-169.16 3358.4,-169.16 3380.81,-146.75 3380.81,-74.75 3411.41,-44.15 3448.39,-44.15 3466.64,-62.4 U12.2@3466.64,-68.9
LED_CLK_OUT13: U13.2 U14.5 | length 342.6
  Top Layer w6: U14.5 3069.95,-158.17 3080.94,-169.16 3161.55,-169.16 3183.96,-146.75 3183.96,-74.75 3214.56,-44.15 3251.54,-44.15 3269.79,-62.4 U13.2@3269.79,-68.9
LED_CLK_OUT14: U14.2 U15.5 | length 342.6
  Top Layer w6: U15.5@2873.15,-127.95 2873.15,-158.17 2884.14,-169.16 2964.76,-169.16 2987.17,-146.75 2987.17,-74.75 3017.77,-44.15 3054.75,-44.15 3072.99,-62.4 U14.2@3072.99,-68.9
LED_CLK_OUT15: U15.2 U16.5 | length 342.6
  Top Layer w6: U16.5@2676.15,-127.95 2676.15,-158.17 2687.14,-169.16 2767.76,-169.16 2790.17,-146.75 2790.17,-74.75 2820.77,-44.15 2857.75,-44.15 2875.99,-62.4 U15.2@2875.99,-68.9
LED_CLK_OUT16: U16.2 U17.5 | length 342.6
  Top Layer w6: U17.5 2479.39,-158.17 2490.39,-169.16 2571,-169.16 2593.41,-146.75 2593.41,-74.75 2624.01,-44.15 2660.99,-44.15 2679.24,-62.4 U16.2@2679.24,-68.9
LED_CLK_OUT17: U17.2 U18.5 | length 342.6
  Top Layer w6: U18.5 2282.54,-158.17 2293.54,-169.16 2374.15,-169.16 2396.56,-146.75 2396.56,-74.75 2427.16,-44.15 2464.14,-44.15 2482.39,-62.4 U17.2@2482.39,-68.9
LED_CLK_OUT18: U18.2 U19.5 | length 342.6
  Top Layer w6: U19.5 2085.69,-158.17 2096.69,-169.16 2177.3,-169.16 2199.71,-146.75 2199.71,-74.75 2230.31,-44.15 2267.29,-44.15 2285.54,-62.4 U18.2@2285.54,-68.9
LED_CLK_OUT19: U19.2 U20.5 | length 342.6
  Top Layer w6: U20.5 1888.84,-158.17 1899.84,-169.16 1980.45,-169.16 2002.86,-146.75 2002.86,-74.75 2033.46,-44.15 2070.44,-44.15 2088.69,-62.4 U19.2@2088.69,-68.9
LED_CLK_OUT20: U20.2 U21.5 | length 342.6
  Top Layer w6: U21.5 1691.99,-158.17 1702.99,-169.16 1783.6,-169.16 1806.01,-146.75 1806.01,-74.75 1836.61,-44.15 1873.59,-44.15 1891.84,-62.4 U20.2@1891.84,-68.9
LED_CLK_OUT21: U21.2 U22.5 | length 342.6
  Top Layer w6: U22.5 1495.14,-158.17 1506.14,-169.16 1586.75,-169.16 1609.16,-146.75 1609.16,-74.75 1639.76,-44.15 1676.74,-44.15 1694.99,-62.4 U21.2@1694.99,-68.9
LED_CLK_OUT22: U22.2 U23.5 | length 342.6
  Top Layer w6: U23.5 1298.29,-158.17 1309.28,-169.16 1389.9,-169.16 1412.31,-146.75 1412.31,-74.75 1442.91,-44.15 1479.89,-44.15 1498.14,-62.4 U22.2@1498.14,-68.9
LED_CLK_OUT23: U23.2 U24.5 | length 342.6
  Top Layer w6: U24.5 1101.44,-158.17 1112.43,-169.16 1193.05,-169.16 1215.46,-146.75 1215.46,-74.75 1246.06,-44.15 1283.04,-44.15 1301.28,-62.4 U23.2@1301.28,-68.9
LED_CLK_OUT24: U24.3 U25.4 | length 319.5
  Top Layer w6: U25.4@872,-130.26 872,-163.96 890.2,-182.16 1000.2,-182.16 1030.61,-151.75 1030.61,-91.43 1050.83,-71.21 U24.3@1069,-71.21
LED_CLK_OUT25: U25.2 U26.5 | length 342.6
  Top Layer w6: U26.5 707.74,-158.17 718.73,-169.16 799.35,-169.16 821.76,-146.75 821.76,-74.75 852.36,-44.15 889.34,-44.15 907.58,-62.4 U25.2@907.58,-68.9
LED_CLK_OUT26: U26.2 U27.5 | length 342.6
  Top Layer w6: U27.5 510.89,-158.17 521.88,-169.16 602.5,-169.16 624.91,-146.75 624.91,-74.75 655.51,-44.15 692.49,-44.15 710.73,-62.4 U26.2@710.73,-68.9
LED_CLK_OUT27: U27.2 U28.5 | length 342.6
  Top Layer w6: U28.5 314.04,-158.17 325.03,-169.16 405.65,-169.16 428.06,-146.75 428.06,-74.75 458.66,-44.15 495.64,-44.15 513.88,-62.4 U27.2@513.88,-68.9
LED_CLK_OUT28: U28.2 U29.5 | length 342.6
  Top Layer w6: U29.5 117.19,-158.17 128.18,-169.16 208.8,-169.16 231.21,-146.75 231.21,-74.75 261.81,-44.15 298.79,-44.15 317.03,-62.4 U28.2@317.03,-68.9
LED_SDI: P1.4 U1.4 | length 1388.6
  Top Layer w6: U1.4 5593.57,-159.65 5614.76,-180.85 6132.28,-180.85 cw(c6132.28,-201.34) 6146.76,-186.85 cw(c6116.14,-217.47) 6159.45,-217.47 P1.4@6159.45,-736.24
  Bottom Layer w6: P1.4@6159.45,-736.24 6159.76,-735.92 v2(6159.76,-495.85)
LED_SDO_1: U1.3 U2.4 | length 319.5
  Top Layer w6: U2.4 5396.57,-161.65 5414.76,-179.85 5524.76,-179.85 5556.76,-147.85 5556.76,-87.53 5575.39,-68.9 U1.3
LED_SDO_2: U2.3 U3.4 | length 319.5
  Top Layer w6: U3.4@5202.56,-130.26 5202.56,-163.96 5220.76,-182.16 5330.76,-182.16 5361.17,-151.75 5361.17,-91.43 5381.39,-71.21 U2.3@5399.56,-71.21
LED_SDO_3: U3.3 U4.4 | length 319.5
  Top Layer w6: U4.4@5005.86,-127.26 5005.86,-160.96 5024.06,-179.16 5134.06,-179.16 5166.06,-147.16 5166.06,-86.84 5184.69,-68.21 U3.3@5202.86,-68.21
LED_SDO_4: U4.3 U5.4 | length 319.5
  Top Layer w6: U5.4@4809.01,-130.26 4809.01,-163.96 4827.21,-182.16 4937.21,-182.16 4967.61,-151.75 4967.61,-91.43 4987.84,-71.21 U4.3@5006.01,-71.21
LED_SDO_5: U5.3 U6.4 | length 319.5
  Top Layer w6: U6.4@4612.16,-130.26 4612.16,-163.96 4630.36,-182.16 4740.36,-182.16 4770.76,-151.75 4770.76,-91.43 4790.98,-71.21 U5.3@4809.16,-71.21
LED_SDO_6: U6.3 U7.4 | length 319.5
  Top Layer w6: U7.4@4415.31,-130.26 4415.31,-163.96 4433.51,-182.16 4543.51,-182.16 4573.91,-151.75 4573.91,-91.43 4594.13,-71.21 U6.3@4612.31,-71.21
LED_SDO_7: U7.3 U8.4 | length 319.5
  Top Layer w6: U8.4@4218.46,-130.26 4218.46,-163.96 4236.66,-182.16 4346.66,-182.16 4377.06,-151.75 4377.06,-91.43 4397.28,-71.21 U7.3@4415.46,-71.21
LED_SDO_8: U8.3 U9.4 | length 319.5
  Top Layer w6: U9.4@4021.61,-130.26 4021.61,-163.96 4039.8,-182.16 4149.8,-182.16 4180.21,-151.75 4180.21,-91.43 4200.43,-71.21 U8.3@4218.61,-71.21
LED_SDO_9: U9.3 U10.4 | length 319.5
  Top Layer w6: U10.4@3824.76,-130.26 3824.76,-163.96 3842.96,-182.16 3952.96,-182.16 3983.36,-151.75 3983.36,-91.43 4003.58,-71.21 U9.3@4021.76,-71.21
LED_SDO_10: U10.3 U11.4 | length 319.5
  Top Layer w6: U11.4@3627.91,-130.26 3627.91,-163.96 3646.1,-182.16 3756.1,-182.16 3786.51,-151.75 3786.51,-91.43 3806.73,-71.21 U10.3@3824.91,-71.21
LED_SDO_11: U11.3 U12.4 | length 319.5
  Top Layer w6: U12.4@3431.06,-130.26 3431.06,-163.96 3449.25,-182.16 3559.25,-182.16 3589.66,-151.75 3589.66,-91.43 3609.88,-71.21 U11.3@3628.06,-71.21
LED_SDO_12: U12.3 U13.4 | length 319.5
  Top Layer w6: U13.4@3234.21,-130.26 3234.21,-163.96 3252.4,-182.16 3362.4,-182.16 3392.81,-151.75 3392.81,-91.43 3413.03,-71.21 U12.3@3431.21,-71.21
LED_SDO_13: U13.3 U14.4 | length 319.5
  Top Layer w6: U14.4@3037.36,-130.26 3037.36,-163.96 3055.55,-182.16 3165.55,-182.16 3195.96,-151.75 3195.96,-91.43 3216.18,-71.21 U13.3@3234.36,-71.21
LED_SDO_14: U14.3 U15.4 | length 319.5
  Top Layer w6: U15.4@2840.56,-130.26 2840.56,-163.96 2858.76,-182.16 2968.76,-182.16 2999.17,-151.75 2999.17,-91.43 3019.39,-71.21 U14.3@3037.56,-71.21
LED_SDO_15: U15.3 U16.4 | length 319.5
  Top Layer w6: U16.4@2643.56,-130.26 2643.56,-163.96 2661.76,-182.16 2771.76,-182.16 2802.17,-151.75 2802.17,-91.43 2822.39,-71.21 U15.3@2840.56,-71.21
LED_SDO_16: U16.3 U17.4 | length 319.5
  Top Layer w6: U17.4@2446.81,-130.26 2446.81,-163.96 2465,-182.16 2575,-182.16 2605.41,-151.75 2605.41,-91.43 2625.63,-71.21 U16.3@2643.81,-71.21
LED_SDO_17: U17.3 U18.4 | length 319.5
  Top Layer w6: U18.4@2249.95,-130.26 2249.95,-163.96 2268.15,-182.16 2378.15,-182.16 2408.56,-151.75 2408.56,-91.43 2428.78,-71.21 U17.3@2446.95,-71.21
LED_SDO_18: U18.3 U19.4 | length 319.5
  Top Layer w6: U19.4@2053.1,-130.26 2053.1,-163.96 2071.3,-182.16 2181.3,-182.16 2211.71,-151.75 2211.71,-91.43 2231.93,-71.21 U18.3@2250.1,-71.21
LED_SDO_19: U19.3 U20.4 | length 319.5
  Top Layer w6: U20.4@1856.25,-130.26 1856.25,-163.96 1874.45,-182.16 1984.45,-182.16 2014.86,-151.75 2014.86,-91.43 2035.08,-71.21 U19.3@2053.25,-71.21
LED_SDO_20: U20.3 U21.4 | length 319.5
  Top Layer w6: U21.4@1659.4,-130.26 1659.4,-163.96 1677.6,-182.16 1787.6,-182.16 1818.01,-151.75 1818.01,-91.43 1838.23,-71.21 U20.3@1856.4,-71.21
LED_SDO_21: U21.3 U22.4 | length 319.5
  Top Layer w6: U22.4@1462.55,-130.26 1462.55,-163.96 1480.75,-182.16 1590.75,-182.16 1621.16,-151.75 1621.16,-91.43 1641.38,-71.21 U21.3@1659.55,-71.21
LED_SDO_22: U22.3 U23.4 | length 319.5
  Top Layer w6: U23.4@1265.7,-130.26 1265.7,-163.96 1283.9,-182.16 1393.9,-182.16 1424.31,-151.75 1424.31,-91.43 1444.53,-71.21 U22.3@1462.7,-71.21
LED_SDO_23: U23.3 U24.4 | length 319.5
  Top Layer w6: U24.4@1068.85,-130.26 1068.85,-163.96 1087.05,-182.16 1197.05,-182.16 1227.46,-151.75 1227.46,-91.43 1247.68,-71.21 U23.3@1265.85,-71.21
LED_SDO_24: U24.2 U25.5 | length 342.6
  Top Layer w6: U25.5 904.59,-158.17 915.58,-169.16 996.2,-169.16 1018.61,-146.75 1018.61,-74.75 1049.21,-44.15 1086.19,-44.15 1104.43,-62.4 U24.2@1104.43,-68.9
LED_SDO_25: U25.3 U26.4 | length 319.5
  Top Layer w6: U26.4@675.15,-130.26 675.15,-163.96 693.35,-182.16 803.35,-182.16 833.76,-151.75 833.76,-91.43 853.98,-71.21 U25.3@872.15,-71.21
LED_SDO_26: U26.3 U27.4 | length 319.5
  Top Layer w6: U27.4@478.3,-130.26 478.3,-163.96 496.5,-182.16 606.5,-182.16 636.91,-151.75 636.91,-91.43 657.13,-71.21 U26.3@675.3,-71.21
LED_SDO_27: U27.3 U28.4 | length 319.5
  Top Layer w6: U28.4@281.45,-130.26 281.45,-163.96 299.65,-182.16 409.65,-182.16 440.06,-151.75 440.06,-91.43 460.28,-71.21 U27.3@478.45,-71.21
LED_SDO_28: U28.3 U29.4 | length 319.5
  Top Layer w6: U29.4@84.6,-130.26 84.6,-163.96 102.8,-182.16 212.8,-182.16 243.21,-151.75 243.21,-91.43 263.43,-71.21 U28.3@281.6,-71.21
pads on no net: U29.2 U29.3

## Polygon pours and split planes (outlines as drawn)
GND on Bottom Layer "gnd_bot" (hatched 45Degree grid 30 track 9.5, remove dead copper, pour order 0): 0,-196.85 0,0 6213.15,0 cw(c6213.15,-25.04) 6238.19,-25.04 6238.19,-814.96 6139.76,-814.96 6139.76,-216.54 ccw(c6120.08,-216.54) 6120.08,-196.85
+5V on Top Layer "Top Layer-+5V" (hatched 45Degree grid 30 track 9.5, remove dead copper, pour order 1): 0,-196.85 0,0 6213.15,0 cw(c6213.15,-25.04) 6238.19,-25.04 6238.19,-814.96 6139.76,-814.96 6139.76,-216.54 ccw(c6120.08,-216.54) 6120.08,-196.85

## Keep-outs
Keep-Out Layer:
  lines w5: 6120.08,-196.85 cw(c6120.08,-216.54) 6139.76,-216.54 6139.76,-814.96 6238.19,-814.96 6238.19,-25.04 ccw(c6213.15,-25.04) 6213.15,0 6139.76,0 5805.12,0 0,0 0,-196.85 6120.08,-196.85 ; 6120.08,-196.85 6120.08,-196.85

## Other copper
Top Layer:
  pour cut-out: 59.65,-44.15 59.95,-43.85 184.95,-43.85 184.95,-157.85 184.64,-158.17 59.95,-158.17 59.95,-44.45
  pour cut-out: 847.06,-44.15 847.35,-43.85 972.35,-43.85 972.35,-157.85 972.04,-158.17 847.35,-158.17 847.35,-44.45
  pour cut-out: 650.06,-44.15 650.35,-43.85 775.35,-43.85 775.35,-157.85 775.04,-158.17 650.35,-158.17 650.35,-44.45
  pour cut-out: 256.5,-44.15 256.8,-43.85 381.8,-43.85 381.8,-157.85 381.49,-158.17 256.8,-158.17 256.8,-44.45
  pour cut-out: 453.5,-44.15 453.8,-43.85 578.8,-43.85 578.8,-157.85 578.49,-158.17 453.8,-158.17 453.8,-44.45
  pour cut-out: 1634.46,-44.15 1634.76,-43.85 1759.76,-43.85 1759.76,-157.85 1759.44,-158.17 1634.76,-158.17 1634.76,-44.45
  pour cut-out: 1437.46,-44.15 1437.76,-43.85 1562.76,-43.85 1562.76,-157.85 1562.44,-158.17 1437.76,-158.17 1437.76,-44.45
  pour cut-out: 1043.91,-44.15 1044.2,-43.85 1169.2,-43.85 1169.2,-157.85 1168.89,-158.17 1044.2,-158.17 1044.2,-44.45
  pour cut-out: 1240.91,-44.15 1241.2,-43.85 1366.2,-43.85 1366.2,-157.85 1365.89,-158.17 1241.2,-158.17 1241.2,-44.45
  pour cut-out: 2421.86,-44.15 2422.16,-43.85 2547.16,-43.85 2547.16,-157.85 2546.84,-158.17 2422.16,-158.17 2422.16,-44.45
  pour cut-out: 2224.86,-44.15 2225.16,-43.85 2350.16,-43.85 2350.16,-157.85 2349.84,-158.17 2225.16,-158.17 2225.16,-44.45
  pour cut-out: 1831.31,-44.15 1831.61,-43.85 1956.61,-43.85 1956.61,-157.85 1956.29,-158.17 1831.61,-158.17 1831.61,-44.45
  pour cut-out: 2028.31,-44.15 2028.61,-43.85 2153.61,-43.85 2153.61,-157.85 2153.29,-158.17 2028.61,-158.17 2028.61,-44.45
  pour cut-out: 3209.26,-44.15 3209.56,-43.85 3334.56,-43.85 3334.56,-157.85 3334.24,-158.17 3209.56,-158.17 3209.56,-44.45
  pour cut-out: 3012.26,-44.15 3012.56,-43.85 3137.56,-43.85 3137.56,-157.85 3137.24,-158.17 3012.56,-158.17 3012.56,-44.45
  pour cut-out: 2618.71,-44.15 2619.01,-43.85 2744.01,-43.85 2744.01,-157.85 2743.69,-158.17 2619.01,-158.17 2619.01,-44.45
  pour cut-out: 2815.71,-44.15 2816.01,-43.85 2941.01,-43.85 2941.01,-157.85 2940.69,-158.17 2816.01,-158.17 2816.01,-44.45
  pour cut-out: 3996.66,-44.15 3996.96,-43.85 4121.96,-43.85 4121.96,-157.85 4121.64,-158.17 3996.96,-158.17 3996.96,-44.45
  pour cut-out: 3799.66,-44.15 3799.96,-43.85 3924.96,-43.85 3924.96,-157.85 3924.64,-158.17 3799.96,-158.17 3799.96,-44.45
  pour cut-out: 3406.11,-44.15 3406.41,-43.85 3531.41,-43.85 3531.41,-157.85 3531.09,-158.17 3406.41,-158.17 3406.41,-44.45
  pour cut-out: 3603.11,-44.15 3603.41,-43.85 3728.41,-43.85 3728.41,-157.85 3728.09,-158.17 3603.41,-158.17 3603.41,-44.45
  pour cut-out: 4784.06,-44.15 4784.36,-43.85 4909.36,-43.85 4909.36,-157.85 4909.05,-158.17 4784.36,-158.17 4784.36,-44.45
  pour cut-out: 4587.06,-44.15 4587.36,-43.85 4712.36,-43.85 4712.36,-157.85 4712.05,-158.17 4587.36,-158.17 4587.36,-44.45
  pour cut-out: 4193.51,-44.15 4193.81,-43.85 4318.81,-43.85 4318.81,-157.85 4318.49,-158.17 4193.81,-158.17 4193.81,-44.45
  pour cut-out: 4390.51,-44.15 4390.81,-43.85 4515.81,-43.85 4515.81,-157.85 4515.49,-158.17 4390.81,-158.17 4390.81,-44.45
  pour cut-out: 5177.91,-44.15 5178.21,-43.85 5303.21,-43.85 5303.21,-157.85 5302.9,-158.17 5178.21,-158.17 5178.21,-44.45
  pour cut-out: 4980.91,-44.15 4981.21,-43.85 5106.21,-43.85 5106.21,-157.85 5105.9,-158.17 4981.21,-158.17 4981.21,-44.45
  pour cut-out: 5374.46,-44.15 5374.76,-43.85 5499.76,-43.85 5499.76,-157.85 5499.45,-158.17 5374.76,-158.17 5374.76,-44.45
  pour cut-out: 5571.46,-44.15 5571.76,-43.85 5696.76,-43.85 5696.76,-157.85 5696.45,-158.17 5571.76,-158.17 5571.76,-44.45

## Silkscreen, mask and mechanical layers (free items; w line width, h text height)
Mechanical 1:
  lines w5: 1,-98.85 cw(c1.43,-98.85) 1.43,-98.43 5805.12,-98.43 5805.12,0 ; 117.19,-107.93 117.19,-88.93 ; 314.04,-107.93 314.04,-88.93 ; 510.89,-107.93 510.89,-88.93 ; 707.74,-107.93 707.74,-88.93 ; 904.59,-107.93 904.59,-88.93 ; 1101.44,-107.93 1101.44,-88.93 ; 1298.29,-107.93 1298.29,-88.93 ; 1495.14,-107.93 1495.14,-88.93 ; 1691.99,-107.93 1691.99,-88.93 ; 1888.84,-107.93 1888.84,-88.93 ; 2085.69,-107.93 2085.69,-88.93 ; 2282.54,-107.93 2282.54,-88.93 ; 2479.39,-107.93 2479.39,-88.93 ; 2676.24,-107.93 2676.24,-88.93 ; 2873.09,-107.93 2873.09,-88.93 ; 3069.94,-107.93 3069.94,-88.93 ; 3266.8,-107.93 3266.8,-88.93 ; 3463.65,-107.93 3463.65,-88.93 ; 3660.5,-107.93 3660.5,-88.93 ; 3857.35,-107.93 3857.35,-88.93 ; 4054.2,-107.93 4054.2,-88.93 ; 4251.05,-107.93 4251.05,-88.93 ; 4447.9,-107.93 4447.9,-88.93 ; 4644.75,-107.93 4644.75,-88.93 ; 4841.6,-107.93 4841.6,-88.93 ; 5038.45,-107.93 5038.45,-88.93 ; 5235.3,-107.93 5235.3,-88.93 ; 5432.15,-107.93 5432.15,-88.93 ; 5977.06,-539.37 6238.19,-539.37 ; 6139.76,-51.85 6139.76,0 ; 5629,-107.93 5629,-88.93 ; 5629,-107.93 5629,-88.93 ; 5629,-107.93 5629,-88.93 ; 5629,-107.93 5629,-88.93
Mechanical 4:
  lines w5: 6120.08,-196.85 cw(c6120.08,-216.54) 6139.76,-216.54 6139.76,-814.96 6238.19,-814.96 6238.19,-25.04 ccw(c6213.15,-25.04) 6213.15,0 6139.76,0 5805.12,0 0,0 0,-196.85 6120.08,-196.85 ; 6120.08,-196.85 6120.08,-196.85
Drill Drawing:
  text "PWB, LED STRIP FLEX" at 7277.47,-4571.16 h157.48
  text "PWB-020218-001" at 7464.48,-4896.95 h127.95
  text "1" at 9889.67,-4956 h78.74
  text "1" at 9700.7,-4959.94 h78.74
Mechanical 17:
  text "PWB, LED STRIP FLEX" at 7320.09,-4645.75 h157.48
  text "PWA-020218-001" at 7514.09,-4936.75 h127.95
  text "1" at 9692.82,-4948.13 h59.06
  text "1" at 9881.8,-4948.13 h59.06
  text "NOTES: /  / 1. ALL ASSEMBLY MATERIALS TO BE RoHS COMPLIANT. /  / 2. MATERIAL: /           • FLEXIBLE METAL CLAD DIELECTRIC IAW                 /             IPC-4204/11 E1E2 O0/0 CU W7 T/T /           • STIFFENER IAW IPC-4203/1-E1E8M1 /  / 3. FINISH:  IMMERSION GOLD /  / ALL EXPOSED CONDUCTIVE PATTERN AREAS NOT COVERED WITH COVERLAY MATERIAL OR OTHER PLATING  / SHALL BE IMMERSION GOLD (0.000030-0.000090 mm) OVER ELECTROLESS NICKEL (0.001-0.006 mm). /  / 4. LEGEND SHALL BE WHITE, PERMANENT, ORGANIC, NON-CONDUCTIVE UV OR EPOXY TYPE INK APPLIED  / TO THE TOP SIDE OF THE BOARD. THERE SHALL BE NO LEGEND ON ANY SOLDERABLE COMPONENT LAND. /  / 5. ALL ASSEMBLY MATERIALS TO BE RoHS COMPLIANT. /  / 6. ANY LABELS OR COMPOSITION OF, APPLIED TO THE BOARD NEED TO BE APPROVIED BY AIRZAI /  / 7. MINIMUM TRACE WIDTHS: /           EXTERNAL: 0.203 mm  INTERNAL: N/A /  / 8. MINIMUM SPACE BETWEEN FEATURES: /          EXTERNAL: 0.15 mm  INTERNAL: N/A /  / 9. Overall Board Thickness: 0.3mm" at -3994,-5043.85 h78.74
Mechanical 18:
  lines w5: -4414.86,-2814.07 -4214.86,-2814.07 ; -4414.86,-439.07 -4214.86,-439.07 ; -4414.86,1935.93 -4214.86,1935.93 ; -1914.86,-5189.07 -1914.86,-4989.07 ; -1914.86,4110.93 -1914.86,4310.93 ; 585.14,-5189.07 585.14,-4989.07 ; 585.14,4110.93 585.14,4310.93 ; 3085.14,-5189.07 3085.14,-4989.07 ; 3085.14,4110.93 3085.14,4310.93 ; 5585.14,-5189.07 5585.14,-4989.07 ; 5585.14,4110.93 5585.14,4310.93 ; 5884.35,-4691.29 10384.35,-4691.29 ; 5884.35,-4449.55 6955.02,-4449.55 ; 5884.35,-4215.5 6955.02,-4215.5 ; 5884.35,-4004.67 6955.02,-4004.67 ; 5885.14,-4989.07 10385.14,-4989.07 ; 6510.14,-4992.27 6510.14,-3792.27 ; 6955.02,-4991.29 6955.02,-3791.29 ; 6955.02,-4324.36 10384.2,-4324.36 ; 7294.98,-3791.29 10384.35,-3791.29 ; 7384.35,-3791.29 5884.35,-3791.29 ; 8085.14,-5189.07 8085.14,-4989.07 ; 8085.14,4110.93 8085.14,4310.93 ; 10007.97,-4991.29 10007.97,-4691.29 ; 10385.14,-3789.07 10385.14,-4989.07 ; 10385.14,-2814.07 10585.14,-2814.07 ; 10385.14,1935.93 10585.14,1935.93 ; 4484.35,-4991.29 5884.35,-4991.29 ; 4484.35,-4991.29 5884.35,-4991.29 ; 4484.35,-4991.29 4484.35,-3791.29 5884.35,-3791.29 ; 5884.35,-4991.29 10384.35,-4991.29 ; 5884.35,-4991.29 10384.35,-4991.29 ; 5884.35,-4991.29 5884.35,-3791.29 ; 10384.35,-4991.29 10384.35,-3791.29 ; 10384.35,-4991.29 10384.35,-3791.29 ; 10385.14,-4989.07 10385.14,4110.93 -4214.86,4110.93 -4214.86,-4989.07 10385.14,-4989.07 ; -4414.86,-5189.07 -4414.86,4310.93 10585.14,4310.93 10585.14,-5189.07 -4414.86,-5189.07
  text "1" at -3183.52,4180.93 h70
  text "2" at -687.86,4180.93 h70
  text "3" at 1801.49,4180.93 h70
  text "4" at 4308.16,4180.93 h70
  text "5" at 6807.14,4180.93 h70
  text "6" at 9312.14,4180.93 h70
  text "A" at -4339.86,3037.93 h70
  text "A" at 10460.14,3037.93 h70
  text "B" at -4339.86,657.93 h70
  text "B" at 10460.14,657.93 h70
  text "C" at -4339.86,-1717.07 h70
  text "C" at 10460.14,-1717.07 h70
  text "AIRZAI PROPRIETARY & CONFIDENTIAL" at 6040.27,-3680.41 h127.95
  text "DATE:" at 6540.65,-3853.49 h45
  text "ENGINEER:" at 5906.79,-3859.79 h45
  text "UNLESS OTHERWISE SPECIFIED" at 4583.96,-3920.42 h59.06
  text "21/01/19" at 6547.98,-3962.11 h59.06
  text "FD" at 6099.66,-3968.37 h78.74
  text "DIMENSIONS ARE IN MM" at 4706,-4046.4 h59.06
  text "PCB DESIGNER:" at 5902.85,-4068.18 h45
  text "DATE:" at 6528.84,-4070.03 h45
  text "D" at -4339.86,-4087.07 h70
  text "D" at 10460.14,-4087.07 h70
  text "AIRZAI" at 7245.97,-4125.29 h127.95
  text "TOLERANCES" at 4906.79,-4172.39 h59.06
  text "21/01/19" at 6547.98,-4176.67 h59.06
  text "DFM" at 6073.29,-4178.26 h78.74
  text "DATE:" at 6528.84,-4282.63 h45
  text "CHECK" at 5902.85,-4284.71 h45
  text "ANGULAR" at 5391.04,-4329.87 h59.06
  text "DECIMALS" at 4587.89,-4341.68 h59.06
  text "TITLE:" at 7006.8,-4388.09 h45
  text "FD" at 6139.03,-4401.44 h78.74
  text ".XX +/- .127MM" at 4540.65,-4499.16 h59.06
  text "+/-" at 5379.23,-4503.1 h59.06
  text "REL" at 5914.66,-4515.7 h45
  text "DATE:" at 6544.59,-4522.78 h45
  text "FD" at 6129.19,-4617.98 h78.74
  text ".XXX +/- .080MM" at 4528.84,-4660.58 h59.06
  text "REV:" at 10030.41,-4755.07 h45
  text "SCALE:" at 6550.1,-4755.85 h45
  text "DWG NO:" at 7001.28,-4763.73 h45
  text "SIZE" at 5914.66,-4766.88 h45
  text "B" at 6118.4,-4897.47 h120
  text "DO NOT SCALE DRAWING" at 4583.96,-4900.74 h70.87
  text "A" at 10114.08,-4916.63 h120
  text "1:1" at 6598.72,-4921.09 h120
  text "SHEET" at 9465.85,-4952.7 h45
  text "OF" at 9729.62,-4952.7 h45
  text "1" at -3183.52,-5119.07 h70
  text "2" at -687.86,-5119.07 h70
  text "3" at 1801.49,-5119.07 h70
  text "4" at 4308.16,-5119.07 h70
  text "5" at 6807.14,-5119.07 h70
  text "6" at 9312.14,-5119.07 h70

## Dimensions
5805.12,125.15 to 6139.76,0 on Mechanical 1
0,0 to 5805.12,0 on Mechanical 1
